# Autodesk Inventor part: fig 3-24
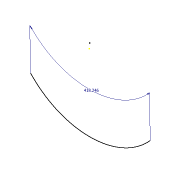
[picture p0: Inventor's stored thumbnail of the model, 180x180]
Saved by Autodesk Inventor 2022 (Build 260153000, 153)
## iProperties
Created: 2018-03
Part Number: fig 3-24
Material: Generic
Document SubType Name: Modeling
Designer: CADCIM 00
Density: 1 g/cm^3
Appearance: Default
Author: CADCIM 00
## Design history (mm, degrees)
sketch "Sketch1"
  geometry: A1 r 252.126 centre (0.845, 16.069) between (-182.963, -156.507) and (188.92, -151.846); 1 further point
  constraints: 2 point on circle, 1 centre point
  dimensions: "d0" = 418.246 dimension on point (0, 0) A1.start A1.end A1.centre A1; "d0" = 418.246 dimension on A1
